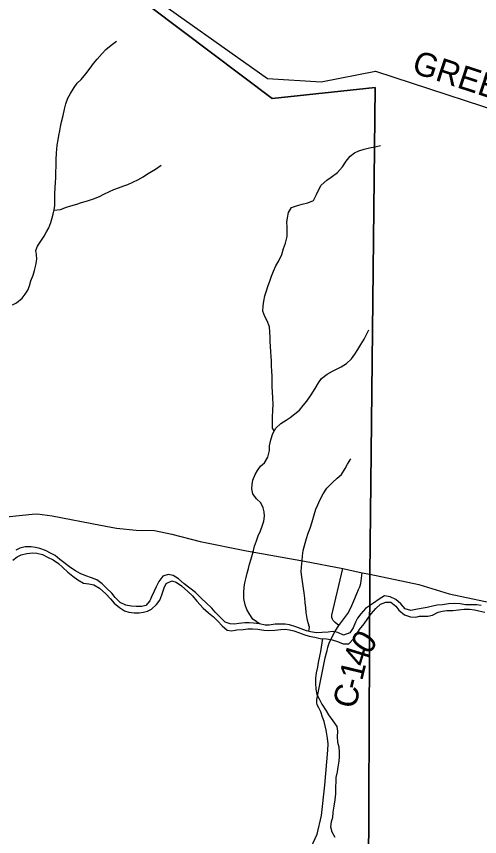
# Model space of a CAD drawing. Extents: x 1578669 to 1989827, y 208020 to 553079.
# Drawn here: x 1762031 to 1767882, y 396225 to 406595 of the extents above; entities that cross this region are included whole.
import ezdxf

# ---------------------------------------------------------------- set-up
doc = ezdxf.new("R2010")
doc.units = 0
for name, color, linetype in [('GM_X_County_Road', 7, 'Continuous'), ('GM_X_County_Road_Text', 7, 'Continuous'), ('GM_X_Minor_River', 7, 'Continuous'), ('GM_X_State_Route', 7, 'Continuous'), ('GM_X_Township', 7, 'Continuous'), ('GM_X_Township_Road', 7, 'Continuous'), ('GM_X_Township_ROW', 7, 'Continuous')]:
    doc.layers.add(name, color=color, linetype=linetype)

msp = doc.modelspace()

# ---------------------------------------------------------------- linework, layer by layer
at = {"layer": 'GM_X_County_Road'}
for points in [[(1763146, 406947), (1763573, 406968), (1765203, 405810), (1765879, 405766), (1766567, 405904), (1768602, 405235)], [(1765933, 398484), (1765947, 398550), (1765955, 398579), (1765960, 398595), (1765967, 398619), (1765983, 398672), (1766005, 398727), (1766057, 398820), (1766105, 398895), (1766193, 399011), (1766219, 399046), (1766257, 399116), (1766308, 399236), (1766353, 399347), (1766368, 399382), (1766381, 399426), (1766399, 399561)]]:
    msp.add_lwpolyline(points, dxfattribs=at)
at = {"layer": 'GM_X_Minor_River'}
for points in [[(1761983, 402947), (1762033, 402973), (1762103, 403031), (1762143, 403085), (1762173, 403135), (1762197, 403189), (1762213, 403251), (1762242, 403323), (1762258, 403383), (1762276, 403451), (1762290, 403525), (1762284, 403583), (1762277, 403633), (1762295, 403689), (1762339, 403751), (1762383, 403817), (1762411, 403871), (1762439, 403923), (1762466, 403987), (1762482, 404046), (1762496, 404096), (1762508, 404150), (1762514, 404202), (1762515, 404276), (1762515, 404350), (1762519, 404432), (1762525, 404494), (1762527, 404554), (1762530, 404631), (1762532, 404699), (1762532, 404785), (1762535, 404867), (1762545, 404967), (1762557, 405033), (1762565, 405088), (1762577, 405146), (1762588, 405200), (1762602, 405262), (1762620, 405342), (1762636, 405420), (1762655, 405490), (1762681, 405562), (1762713, 405622), (1762759, 405694), (1762799, 405750), (1762849, 405798), (1762908, 405870), (1762964, 405942), (1763004, 405998), (1763050, 406056), (1763112, 406124), (1763162, 406176), (1763227, 406230), (1763297, 406280)], [(1765288, 401354), (1765267, 401389), (1765265, 401451), (1765267, 401529), (1765271, 401611), (1765276, 401691), (1765272, 401768), (1765266, 401848), (1765263, 401912), (1765261, 401984), (1765261, 402040), (1765257, 402112), (1765255, 402174), (1765252, 402241), (1765248, 402295), (1765244, 402353), (1765240, 402425), (1765236, 402481), (1765235, 402533), (1765231, 402605), (1765227, 402672), (1765199, 402744), (1765168, 402800), (1765144, 402866), (1765146, 402936), (1765156, 402993), (1765170, 403061), (1765191, 403127), (1765207, 403179), (1765235, 403261), (1765253, 403311), (1765279, 403373), (1765310, 403441), (1765344, 403503), (1765382, 403585), (1765406, 403661), (1765432, 403729), (1765451, 403813), (1765453, 403874), (1765451, 403940), (1765449, 403990), (1765454, 404048), (1765468, 404114), (1765508, 404180), (1765582, 404204), (1765642, 404220), (1765714, 404237), (1765782, 404269), (1765822, 404341), (1765846, 404399), (1765879, 404459), (1765951, 404525), (1766007, 404563), (1766087, 404623), (1766149, 404693), (1766197, 404765), (1766248, 404829), (1766300, 404869), (1766356, 404897), (1766422, 404915), (1766492, 404932), (1766560, 404944), (1766630, 404962)], [(1762507, 404146), (1762588, 404153), (1762662, 404181), (1762718, 404199), (1762794, 404221), (1762854, 404243), (1762930, 404263), (1763004, 404288), (1763080, 404318), (1763136, 404348), (1763208, 404380), (1763260, 404408), (1763320, 404428), (1763386, 404451), (1763439, 404469), (1763509, 404503), (1763563, 404529), (1763633, 404567), (1763685, 404603), (1763789, 404663), (1763861, 404716)], [(1765101, 398914), (1765019, 398974), (1764973, 399045), (1764941, 399097), (1764920, 399155), (1764904, 399237), (1764902, 399317), (1764906, 399380), (1764918, 399434), (1764935, 399502), (1764947, 399556), (1764961, 399614), (1764975, 399670), (1764997, 399738), (1765014, 399794), (1765026, 399844), (1765040, 399896), (1765064, 399964), (1765086, 400026), (1765113, 400092), (1765139, 400162), (1765155, 400213), (1765165, 400275), (1765161, 400329), (1765149, 400383), (1765120, 400445), (1765062, 400495), (1765018, 400558), (1765006, 400622), (1765011, 400678), (1765019, 400730), (1765045, 400804), (1765075, 400854), (1765113, 400910), (1765165, 400952), (1765208, 401022), (1765226, 401106), (1765230, 401166), (1765244, 401242), (1765271, 401323), (1765307, 401387), (1765373, 401446), (1765437, 401490), (1765489, 401524), (1765549, 401568), (1765607, 401616), (1765653, 401674), (1765698, 401732), (1765756, 401810), (1765804, 401890), (1765848, 401960), (1765886, 402018), (1765957, 402072), (1766025, 402108), (1766075, 402134), (1766135, 402166), (1766201, 402205), (1766263, 402267), (1766305, 402325), (1766345, 402385), (1766383, 402445), (1766424, 402513), (1766450, 402563), (1766484, 402631)], [(1765727, 398819), (1765732, 398872), (1765718, 398926), (1765704, 398982), (1765691, 399058), (1765687, 399122), (1765679, 399181), (1765673, 399239), (1765665, 399307), (1765658, 399363), (1765650, 399421), (1765638, 399507), (1765630, 399572), (1765633, 399630), (1765639, 399716), (1765645, 399774), (1765655, 399844), (1765678, 399936), (1765696, 399992), (1765718, 400060), (1765740, 400124), (1765766, 400203), (1765793, 400295), (1765815, 400365), (1765837, 400421), (1765863, 400479), (1765905, 400559), (1765954, 400629), (1766022, 400701), (1766084, 400755), (1766136, 400803), (1766182, 400879), (1766212, 400933), (1766257, 401003)], [(1765101, 398914), (1765027, 398924), (1764969, 398928), (1764917, 398927), (1764841, 398917), (1764787, 398911), (1764733, 398913), (1764669, 398935), (1764601, 399004), (1764540, 399062), (1764500, 399114), (1764426, 399181), (1764370, 399237), (1764295, 399309), (1764221, 399366), (1764151, 399420), (1764077, 399484), (1764009, 399527), (1763948, 399537), (1763882, 399519), (1763831, 399451), (1763795, 399381), (1763771, 399327), (1763739, 399257), (1763717, 399205), (1763664, 399147), (1763614, 399135), (1763545, 399135), (1763481, 399138), (1763411, 399150), (1763343, 399186), (1763279, 399249), (1763235, 399301), (1763168, 399365), (1763114, 399421), (1763046, 399470), (1762980, 399496), (1762906, 399520), (1762836, 399553), (1762777, 399585), (1762719, 399621), (1762579, 399730), (1762519, 399778), (1762468, 399806), (1762396, 399843), (1762326, 399869), (1762270, 399879), (1762216, 399887), (1762142, 399888), (1762074, 399872), (1762024, 399848)], [(1761986, 399718), (1762038, 399760), (1762090, 399786), (1762162, 399805), (1762236, 399813), (1762290, 399809), (1762360, 399793), (1762425, 399758), (1762493, 399724), (1762561, 399678), (1762615, 399628), (1762681, 399567), (1762744, 399517)], [(1762744, 399517), (1762808, 399473), (1762880, 399430), (1762946, 399422), (1763008, 399408), (1763080, 399365), (1763159, 399293), (1763221, 399231), (1763267, 399178), (1763333, 399120), (1763394, 399080), (1763452, 399062), (1763520, 399055), (1763582, 399055), (1763634, 399063), (1763686, 399073), (1763738, 399101), (1763802, 399161), (1763843, 399215), (1763869, 399283), (1763899, 399369), (1763921, 399423), (1763995, 399459), (1764047, 399442), (1764117, 399396), (1764197, 399322), (1764254, 399267), (1764308, 399203), (1764390, 399111), (1764458, 399054), (1764521, 399002), (1764575, 398948), (1764631, 398889), (1764693, 398833), (1764749, 398827), (1764815, 398837), (1764896, 398844), (1764954, 398850), (1765012, 398852), (1765082, 398846), (1765156, 398836), (1765220, 398829), (1765296, 398835), (1765370, 398845), (1765426, 398847), (1765480, 398841), (1765536, 398826), (1765606, 398800), (1765660, 398782), (1765730, 398760), (1765799, 398745), (1765869, 398731), (1765947, 398725), (1766019, 398713), (1766089, 398690), (1766157, 398662), (1766229, 398660), (1766289, 398726), (1766327, 398780), (1766365, 398844), (1766422, 398916), (1766470, 398982), (1766512, 399040), (1766572, 399108), (1766630, 399164), (1766696, 399189), (1766762, 399189), (1766824, 399137), (1766864, 399087), (1766932, 399030), (1767009, 399002), (1767075, 398998), (1767125, 399010), (1767177, 399013), (1767229, 399011), (1767289, 399025), (1767357, 399063), (1767409, 399077), (1767469, 399085), (1767543, 399084), (1767617, 399090), (1767687, 399100), (1767755, 399102), (1767819, 399090), (1767871, 399081), (1767947, 399063)], [(1767901, 399147), (1767847, 399156), (1767771, 399154), (1767705, 399156), (1767637, 399166), (1767564, 399173), (1767490, 399167), (1767414, 399157), (1767346, 399149), (1767286, 399137), (1767218, 399122), (1767144, 399110), (1767078, 399094), (1767012, 399082), (1766944, 399106), (1766886, 399169), (1766822, 399221), (1766754, 399257), (1766681, 399270), (1766614, 399228), (1766542, 399176), (1766492, 399144), (1766440, 399110), (1766380, 399042), (1766338, 398988), (1766314, 398936), (1766285, 398864), (1766241, 398800), (1766161, 398772), (1766091, 398807), (1766024, 398819), (1765970, 398811), (1765892, 398805), (1765820, 398803), (1765748, 398814), (1765696, 398828), (1765628, 398852), (1765560, 398878), (1765482, 398903), (1765428, 398911), (1765370, 398911), (1765298, 398909), (1765224, 398900), (1765172, 398900), (1765101, 398914)], [(1765898, 398729), (1765889, 398673), (1765881, 398621), (1765871, 398565), (1765859, 398507), (1765844, 398424), (1765834, 398368), (1765818, 398294), (1765810, 398228), (1765808, 398166), (1765815, 398090), (1765827, 398020), (1765855, 397967), (1765891, 397899), (1765946, 397813), (1765972, 397763), (1766030, 397690), (1766077, 397618), (1766087, 397556), (1766083, 397484), (1766089, 397418), (1766103, 397359), (1766108, 397287), (1766110, 397233), (1766104, 397177), (1766090, 397103), (1766082, 397045), (1766067, 396973), (1766065, 396915), (1766063, 396858), (1766063, 396764), (1766054, 396690), (1766040, 396608), (1766028, 396534), (1766022, 396464), (1766007, 396410), (1765997, 396348), (1766017, 396287), (1766055, 396219)]]:
    msp.add_lwpolyline(points, dxfattribs=at)
at = {"layer": 'GM_X_State_Route'}
msp.add_lwpolyline([(1761609, 400240), (1762230, 400300), (1762294, 400305), (1762484, 400281), (1763093, 400163), (1763296, 400126), (1763542, 400099), (1763777, 400093), (1763996, 400047), (1764351, 399957), (1764938, 399837), (1765670, 399708), (1766156, 399613), (1766399, 399561), (1766495, 399541), (1767115, 399410), (1767496, 399294), (1768175, 399151)], dxfattribs=at)
at = {"layer": 'GM_X_Township'}
for points in [[(1766452, 389999), (1766495, 399541), (1766565, 405696), (1765263, 405555), (1763728, 406710)], [(1763728, 406710), (1765263, 405555), (1766565, 405696), (1766495, 399541), (1766452, 389999)]]:
    msp.add_lwpolyline(points, dxfattribs=at)
at = {"layer": 'GM_X_Township_Road'}
msp.add_lwpolyline([(1766105, 398895), (1766058, 398931), (1766048, 398939), (1766039, 398948), (1766031, 398958), (1766022, 398975), (1766016, 398993), (1766014, 399013), (1766015, 399026), (1766156, 399613)], dxfattribs=at)
at = {"layer": 'GM_X_Township_ROW'}
msp.add_lwpolyline([(1765753, 396093), (1765831, 396257), (1765885, 396491), (1765925, 396876), (1765966, 397317), (1765970, 397396), (1765962, 397469), (1765942, 397570), (1765918, 397678), (1765899, 397736), (1765877, 397801), (1765853, 397852), (1765831, 397889), (1765825, 397917), (1765826, 397960), (1765879, 398233), (1765933, 398484)], dxfattribs=at)

# ---------------------------------------------------------------- texts
at = {"layer": 'GM_X_County_Road_Text'}
for s, rotation, p in [('GREEN', 341.761, (1767012, 405889)), ('0', 56.0476, (1766484, 398513)), ('4', 72.8895, (1766440, 398359)), ('1', 76.3374, (1766398, 398185)), ('C', 76.3374, (1766312, 397829)), ('-', 76.3374, (1766369, 398067))]:
    msp.add_text(s, height=300, rotation=rotation, dxfattribs=at).set_placement(p)

doc.saveas('drawing.dxf')
